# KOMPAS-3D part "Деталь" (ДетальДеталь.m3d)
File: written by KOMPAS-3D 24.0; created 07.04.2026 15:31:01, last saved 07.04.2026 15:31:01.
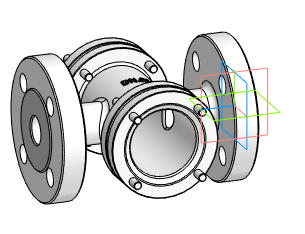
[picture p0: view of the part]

Document properties: Автор: Main; Полное имя файла: D:\DN.ru Аутсерс\Стекло смотровое DN.ru\Исходники\Стекло смотровое DN.ru SG2-34G-F тип В ГОСТ 21836-2021 Ду20 Ру40, углеродистая сталь, фланцевое\ДетальДеталь.m3d

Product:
- Body: Твердое тело1  | qty 1
- Part/product: Деталь
    additional columns: Типовые

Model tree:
1. Твердое тело1  (labels: Твердое тело1)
